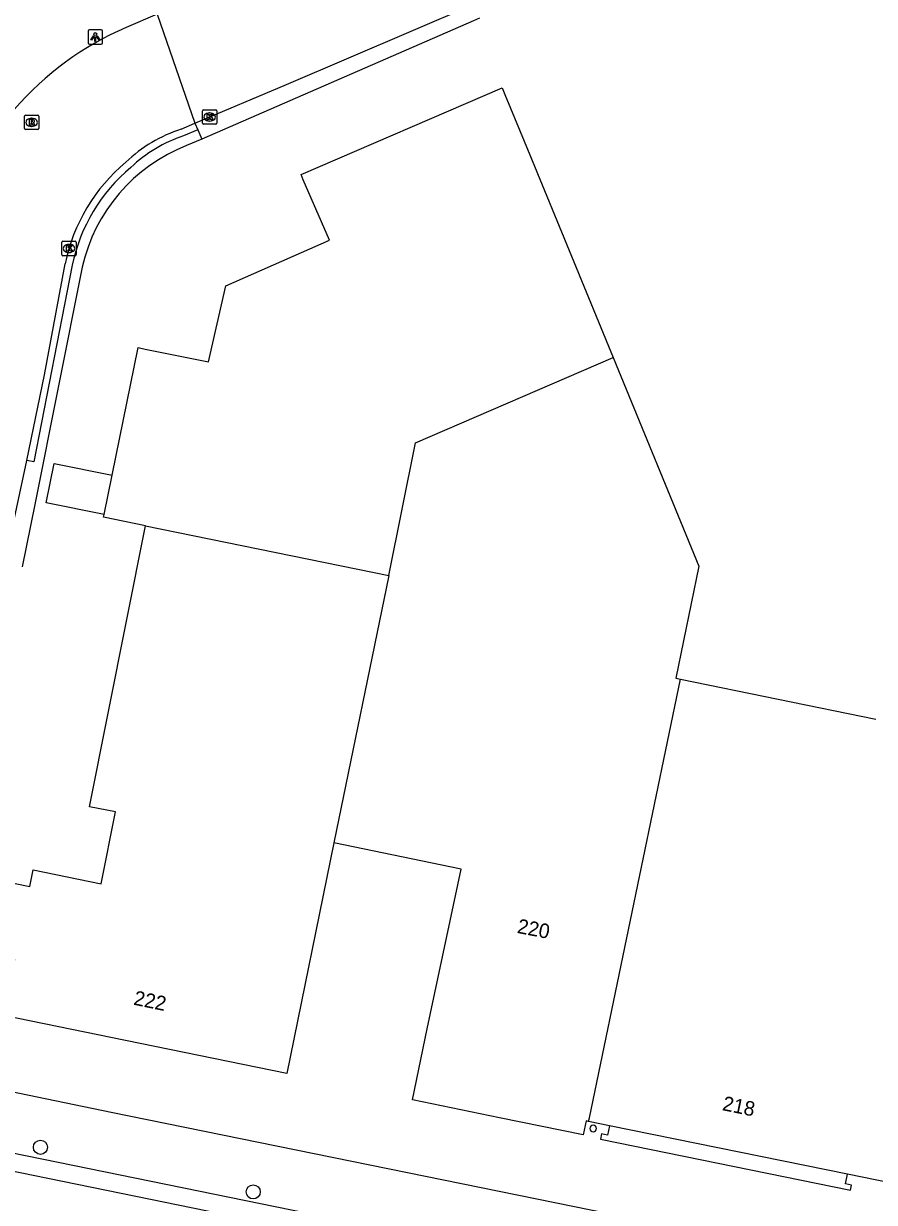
# Model space of a CAD drawing. Extents: x 158087 to 159494, y 382905 to 383981.
# Drawn here: x 158806.5 to 158865.2, y 382994.2 to 383075.4 of the extents above; entities that cross this region are included whole.
import ezdxf

# ---------------------------------------------------------------- set-up
doc = ezdxf.new("R2010")
doc.units = 0
for name, color, linetype in [('IMGEO_Boom', 7, 'Continuous'), ('IMGEO_Kolk', 7, 'Continuous'), ('IMGEO_Lichtpunt', 7, 'Continuous'), ('IMGEO_Pand', 7, 'Continuous'), ('IMGEO_Pand_nummerreeks', 7, 'Continuous'), ('IMGEO_Pand_overbouw', 7, 'Continuous'), ('IMGEO_Rijbaan_lokaal_gesloten', 7, 'Continuous'), ('IMGEO_Rijbaan_lokaal_open', 7, 'Continuous'), ('IMGEO_Rioolput', 7, 'Continuous'), ('IMGEO_Voetpad_open', 7, 'Continuous')]:
    doc.layers.add(name, color=color, linetype=linetype)

msp = doc.modelspace()

# ---------------------------------------------------------------- linework, layer by layer
at = {"layer": 'IMGEO_Boom'}
for centre in [(158807.682, 382997.959), (158822.362, 382994.883)]:
    msp.add_circle(centre, 0.489, dxfattribs=at)
at = {"layer": 'IMGEO_Kolk'}
for p, q in [((158818.856, 383068.566), (158818.856, 383069.418)), ((158818.931, 383069.492), (158819.783, 383069.492)), ((158819.344, 383069.272), (158819.369, 383069.272)), ((158819.857, 383069.418), (158819.857, 383068.566)), ((158819.783, 383068.492), (158818.931, 383068.492)), ((158819.367, 383068.712), (158819.342, 383068.712)), ((158809.151, 383059.507), (158809.151, 383060.359)), ((158809.226, 383060.433), (158810.078, 383060.433)), ((158809.639, 383060.213), (158809.664, 383060.213)), ((158810.152, 383060.359), (158810.152, 383059.507)), ((158810.078, 383059.433), (158809.226, 383059.433)), ((158809.662, 383059.653), (158809.637, 383059.653))]:
    msp.add_line(p, q, dxfattribs=at)
for points in [[(158818.856, 383068.566), (158818.856, 383069.418)], [(158818.931, 383069.492), (158819.783, 383069.492)], [(158819.177, 383069.192), (158819.3, 383069.192), (158819.3, 383069.041), (158819.43, 383069.192), (158819.594, 383069.192), (158819.448, 383069.041), (158819.601, 383068.792), (158819.449, 383068.792), (158819.364, 383068.956), (158819.3, 383068.889), (158819.3, 383068.792), (158819.177, 383068.792), (158819.177, 383069.192)], [(158819.857, 383069.418), (158819.857, 383068.566)], [(158819.783, 383068.492), (158818.931, 383068.492)], [(158809.151, 383059.507), (158809.151, 383060.359)], [(158809.226, 383060.433), (158810.078, 383060.433)], [(158809.472, 383060.133), (158809.595, 383060.133), (158809.595, 383059.982), (158809.725, 383060.133), (158809.889, 383060.133), (158809.743, 383059.982), (158809.896, 383059.733), (158809.744, 383059.733), (158809.659, 383059.897), (158809.595, 383059.83), (158809.595, 383059.733), (158809.472, 383059.733), (158809.472, 383060.133)], [(158810.152, 383060.359), (158810.152, 383059.507)], [(158810.078, 383059.433), (158809.226, 383059.433)]]:
    msp.add_lwpolyline(points, dxfattribs=at)
for centre, start, end in [((158818.933, 383069.416), 91.55205, 178.44795), ((158818.933, 383069.416), 91.55205, 178.44795), ((158819.781, 383069.416), 1.55205, 88.44795), ((158819.781, 383069.416), 1.55205, 88.44795), ((158818.933, 383068.568), 181.55205, 268.44795), ((158818.933, 383068.568), 181.55205, 268.44795), ((158819.781, 383068.568), 271.55205, 358.44795), ((158819.781, 383068.568), 271.55205, 358.44795), ((158809.228, 383060.357), 91.55205, 178.44795), ((158809.228, 383060.357), 91.55205, 178.44795), ((158810.076, 383060.357), 1.55205, 88.44795), ((158810.076, 383060.357), 1.55205, 88.44795), ((158809.228, 383059.509), 181.55205, 268.44795), ((158809.228, 383059.509), 181.55205, 268.44795), ((158810.076, 383059.509), 271.55205, 358.44795), ((158810.076, 383059.509), 271.55205, 358.44795)]:
    msp.add_arc(centre, 0.0765, start, end, dxfattribs=at)
for centre, major_axis, ratio, start_param, end_param in [((158819.343, 383068.992), (-0.387, 0.002), 0.722429, 4.712389, 7.853982), ((158819.368, 383068.992), (-0.39, 0.002), 0.717154, 1.570796, 4.712389), ((158809.638, 383059.933), (-0.387, 0.002), 0.722429, 4.712389, 7.853982), ((158809.663, 383059.933), (-0.39, 0.002), 0.717154, 1.570796, 4.712389)]:
    msp.add_ellipse(centre, major_axis=major_axis, ratio=ratio, start_param=start_param, end_param=end_param, dxfattribs=at)
at = {"layer": 'IMGEO_Lichtpunt'}
for p, q in [((158810.968, 383074.917), (158810.968, 383074.11)), ((158810.968, 383074.917), (158810.968, 383074.11)), ((158811.87, 383075.012), (158811.062, 383075.012)), ((158811.87, 383075.012), (158811.062, 383075.012)), ((158811.964, 383074.11), (158811.964, 383074.917)), ((158811.964, 383074.11), (158811.964, 383074.917)), ((158811.062, 383074.016), (158811.87, 383074.016)), ((158811.062, 383074.016), (158811.87, 383074.016))]:
    msp.add_line(p, q, dxfattribs=at)
for points in [[(158811.342, 383074.581), (158811.381, 383074.553), (158811.193, 383074.291), (158811.155, 383074.318), (158811.342, 383074.581)], [(158811.444, 383074.533), (158811.491, 383074.533), (158811.491, 383074.211), (158811.444, 383074.211), (158811.444, 383074.533)], [(158811.554, 383074.553), (158811.592, 383074.58), (158811.779, 383074.318), (158811.74, 383074.29), (158811.554, 383074.553)]]:
    msp.add_lwpolyline(points, dxfattribs=at)
msp.add_circle((158811.467, 383074.715), 0.0994, dxfattribs=at)
for centre, start, end in [((158811.062, 383074.917), 90, 180), ((158811.062, 383074.917), 90, 180), ((158811.87, 383074.917), 0, 90), ((158811.87, 383074.917), 0, 90), ((158811.062, 383074.11), 180, 270), ((158811.062, 383074.11), 180, 270), ((158811.87, 383074.11), 270, 0), ((158811.87, 383074.11), 270, 360)]:
    msp.add_arc(centre, 0.0946, start, end, dxfattribs=at)
at = {"layer": 'IMGEO_Pand'}
for points in [[(158812.631, 383044.289), (158814.431, 383053.094), (158814.905, 383052.997), (158819.271, 383052.105), (158820.475, 383057.358), (158827.618, 383060.492), (158825.82, 383064.663), (158825.666, 383065.019), (158839.541, 383071.003), (158839.731, 383070.541), (158841.445, 383066.38), (158847.197, 383052.411)], [(158831.715, 383037.39), (158833.572, 383046.532), (158847.197, 383052.411)], [(158847.197, 383052.411), (158853.12, 383038.028), (158851.536, 383030.298), (158851.85, 383030.234)], [(158812.078, 383041.581), (158808.08, 383042.398), (158808.633, 383045.106), (158812.631, 383044.289)], [(158812.078, 383041.581), (158812.631, 383044.289)], [(158814.931, 383040.798), (158812.043, 383041.411), (158812.078, 383041.581)], [(158827.937, 383018.939), (158824.69, 383003.051), (158813.56, 383005.326), (158805.122, 383007.05), (158805.909, 383010.903), (158801.501, 383011.804), (158802.53, 383016.84), (158806.939, 383015.939), (158807.173, 383017.085), (158811.862, 383016.127), (158812.854, 383021.076), (158811.055, 383021.437), (158814.931, 383040.798)], [(158814.931, 383040.798), (158831.715, 383037.39)], [(158831.715, 383037.39), (158827.937, 383018.939)], [(158845.507, 382999.741), (158845.561, 383000), (158851.85, 383030.234)], [(158851.85, 383030.234), (158865.33, 383027.473)], [(158845.507, 382999.741), (158845.331, 382999.777), (158845.135, 382998.817), (158839.363, 383000), (158833.357, 383001.231), (158834.361, 383006.129), (158836.719, 383017.145), (158827.937, 383018.939)], [(158867.293, 382995.293), (158863.364, 382996.095), (158846.94, 382999.448), (158845.507, 382999.741)]]:
    msp.add_lwpolyline(points, dxfattribs=at)
for start, end in [(0, 180), (180, 0)]:
    msp.add_arc((158845.82, 382999.248), 0.225, start, end, dxfattribs=at)
at = {"layer": 'IMGEO_Pand_overbouw'}
msp.add_lwpolyline([(158863.364, 382996.095), (158846.94, 382999.448), (158846.807, 382998.794), (158846.395, 382998.878), (158846.323, 382998.525), (158863.568, 382994.991), (158863.64, 382995.344), (158863.228, 382995.428)], close=True, dxfattribs=at)
at = {"layer": 'IMGEO_Rijbaan_lokaal_gesloten'}
for points in [[(159016.279, 382954.495), (159013.768, 382955.082), (159011.081, 382955.558), (158978.234, 382962.337), (158956.045, 382966.811), (158953.939, 382967.303), (158917.851, 382974.619), (158915.417, 382975.169), (158803.465, 382998.005)], [(159031.685, 382949.921), (159015.031, 382953.509), (158803.226, 382996.829)]]:
    msp.add_lwpolyline(points, dxfattribs=at)
at = {"layer": 'IMGEO_Rijbaan_lokaal_open'}
for points in [[(158818.333, 383068.56), (158824.654, 383071.232), (158837.57, 383076.747)], [(158815.746, 383076.096), (158813.597, 383075.162)], [(158815.746, 383076.096), (158818.333, 383068.56)], [(158817.395, 383068.163), (158818.333, 383068.56)], [(158806.731, 383045.313), (158807.971, 383051.215), (158809.383, 383058.871)], [(158805.259, 383038.227), (158805.761, 383040.697), (158806.731, 383045.313)]]:
    msp.add_lwpolyline(points, dxfattribs=at)
for centre, radius, start, end in [((158821.836, 383055.818), 21.026, 113.07071, 139.32019), ((158820.528, 383058.597), 10.066, 108.13112, 133.66831), ((158821.481, 383056.388), 12.35, 129.7919, 168.40332)]:
    msp.add_arc(centre, radius, start, end, dxfattribs=at)
at = {"layer": 'IMGEO_Rioolput'}
for p, q in [((158806.575, 383068.198), (158806.575, 383069.05)), ((158806.65, 383069.124), (158807.502, 383069.124)), ((158807.576, 383069.05), (158807.576, 383068.198)), ((158807.086, 383068.344), (158807.061, 383068.344)), ((158807.063, 383068.904), (158807.088, 383068.904)), ((158807.502, 383068.124), (158806.65, 383068.124))]:
    msp.add_line(p, q, dxfattribs=at)
for points in [[(158806.575, 383068.198), (158806.575, 383069.05)], [(158806.65, 383069.124), (158807.502, 383069.124)], [(158807.576, 383069.05), (158807.576, 383068.198)], [(158807.164, 383068.822), (158806.912, 383068.824), (158806.912, 383068.424)], [(158806.912, 383068.424), (158807.036, 383068.424), (158807.036, 383068.586), (158807.047, 383068.586)], [(158807.09, 383068.743), (158807.036, 383068.743), (158807.036, 383068.662)], [(158807.036, 383068.662), (158807.088, 383068.662)], [(158807.094, 383068.557), (158807.165, 383068.424), (158807.305, 383068.424), (158807.24, 383068.55)], [(158807.502, 383068.124), (158806.65, 383068.124)]]:
    msp.add_lwpolyline(points, dxfattribs=at)
for centre, radius, start, end in [((158806.652, 383069.048), 0.0765, 91.55205, 178.44795), ((158806.652, 383069.048), 0.0765, 91.55205, 178.44795), ((158807.5, 383069.048), 0.0765, 1.55205, 88.44795), ((158807.5, 383069.048), 0.0765, 1.55205, 88.44795), ((158806.652, 383068.2), 0.0765, 181.55205, 268.44795), ((158806.652, 383068.2), 0.0765, 181.55205, 268.44795), ((158807.046, 383068.533), 0.0533, 26.02933, 88.69889), ((158807.072, 383068.851), 0.19, 274.7715, 282.96867), ((158807.096, 383068.647), 0.0964, 77.00612, 93.18647), ((158807.11, 383068.704), 0.0378, 276.66336, 79.67722), ((158807.163, 383068.712), 0.109, 350.36119, 89.41601), ((158807.161, 383068.712), 0.112, 277.58423, 350.98172), ((158807.145, 383068.497), 0.108, 29.51342, 73.79051), ((158807.5, 383068.2), 0.0765, 271.55205, 358.44795), ((158807.5, 383068.2), 0.0765, 271.55205, 358.44795)]:
    msp.add_arc(centre, radius, start, end, dxfattribs=at)
for centre, major_axis, ratio, start_param, end_param in [((158807.062, 383068.624), (-0.387, 0.002), 0.722429, 4.712389, 7.853982), ((158807.087, 383068.624), (-0.39, 0.002), 0.717154, 1.570796, 4.712389)]:
    msp.add_ellipse(centre, major_axis=major_axis, ratio=ratio, start_param=start_param, end_param=end_param, dxfattribs=at)
at = {"layer": 'IMGEO_Voetpad_open'}
for points in [[(158837.977, 383075.801), (158837.572, 383075.626), (158818.806, 383067.474)], [(158818.333, 383068.56), (158818.533, 383068.101)], [(158818.533, 383068.101), (158817.551, 383067.688)], [(158818.806, 383067.474), (158817.768, 383067.023)], [(158818.533, 383068.101), (158818.806, 383067.474)], [(158810.559, 383058.63), (158807.3, 383042.268), (158806.424, 383037.984)], [(158809.875, 383058.777), (158807.219, 383045.208), (158806.731, 383045.313)], [(158801.731, 383002.602), (158804.889, 383001.97), (158812.55, 383000.385), (158882.725, 382986.097), (158965.13, 382969.191), (158987.319, 382964.716), (159020.488, 382957.863)]]:
    msp.add_lwpolyline(points, dxfattribs=at)
for centre, radius, start, end in [((158820.529, 383058.594), 9.569, 108.13395, 133.6681), ((158822.065, 383056.04), 11.794, 111.36692, 167.31253), ((158821.53, 383056.362), 11.903, 129.73253, 168.29496)]:
    msp.add_arc(centre, radius, start, end, dxfattribs=at)

# ---------------------------------------------------------------- texts
at = {"layer": 'IMGEO_Pand_nummerreeks'}
for s, rotation, p in [('220', 349.14359, (158840.527, 383012.745)), ('222', 348.44983, (158814.058, 383007.796)), ('218', 348.44657, (158854.686, 383000.525))]:
    msp.add_text(s, height=1, rotation=rotation, dxfattribs=at).set_placement(p)

doc.saveas('drawing.dxf')
